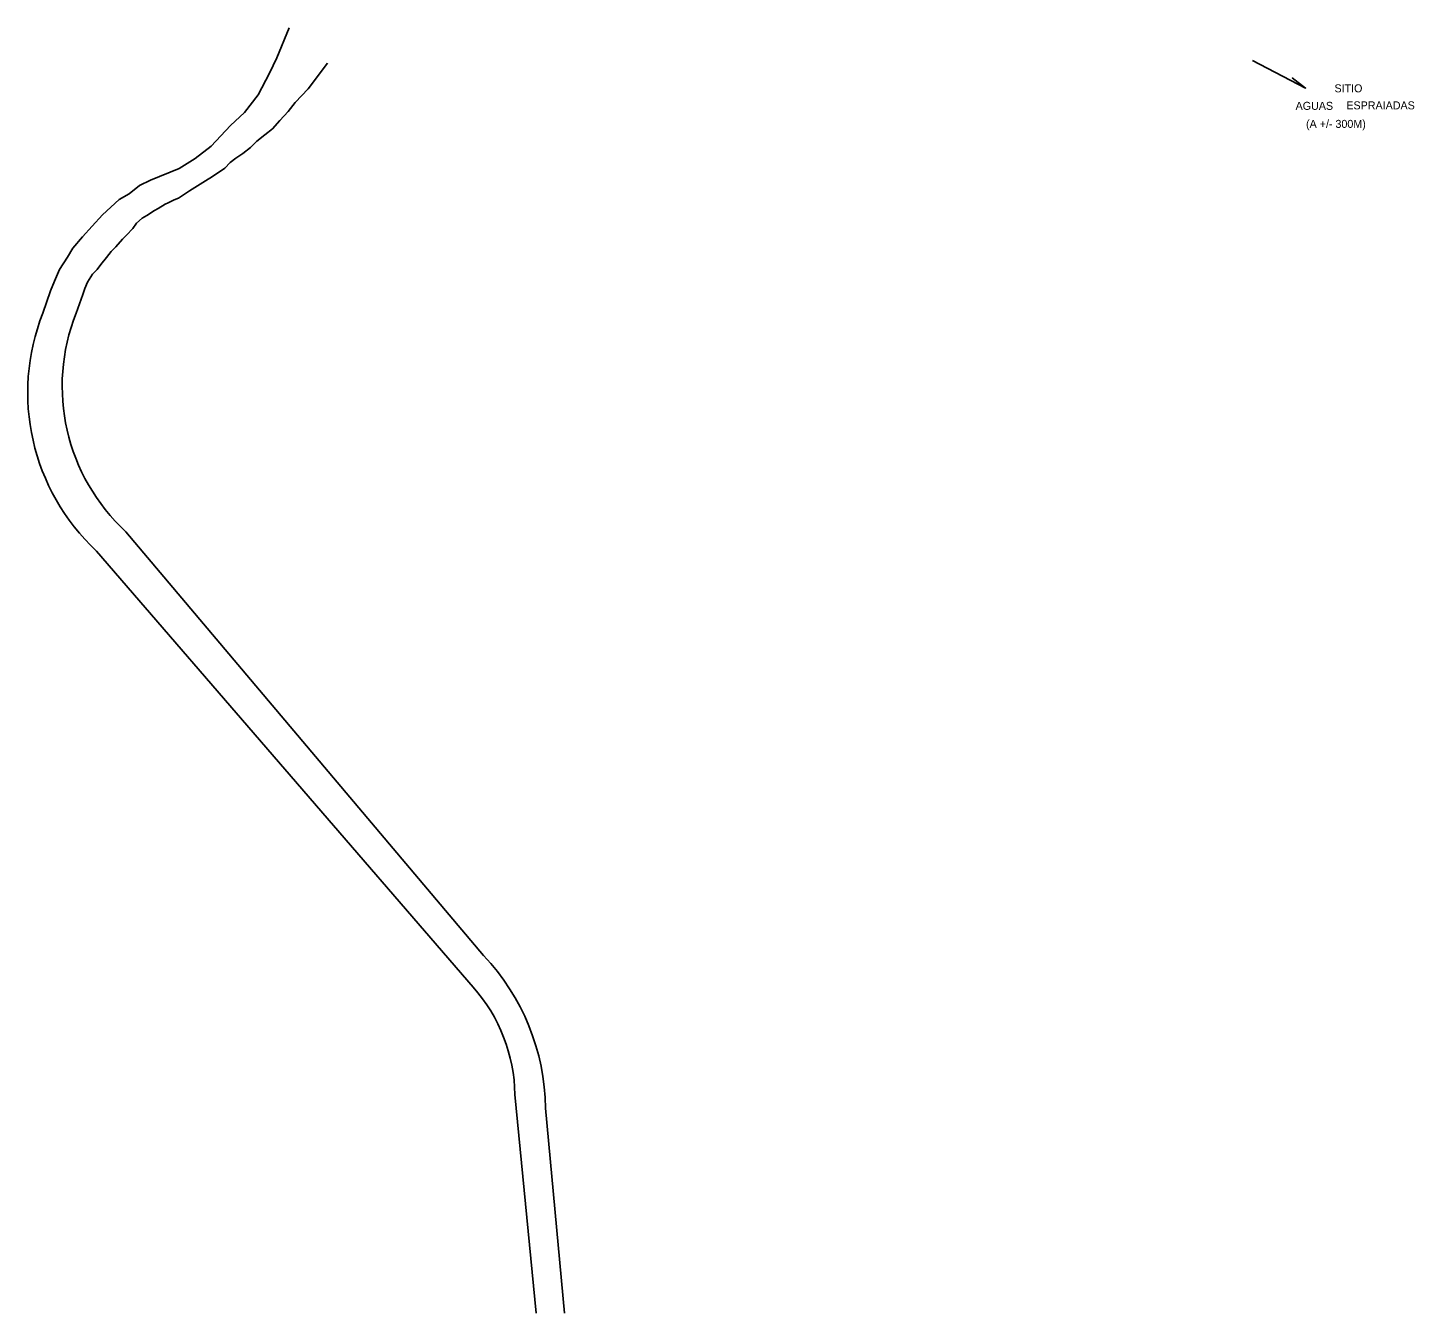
# Model space of a CAD drawing. Extents: x 325899 to 364828, y 7568995 to 7592502.
# Drawn here: x 343420 to 344113, y 7587502 to 7588145 of the extents above; entities that cross this region are included whole.
import ezdxf

# ---------------------------------------------------------------- set-up
doc = ezdxf.new("R2010")
doc.units = 0
doc.layers.add('EDIFIDENTIF', color=7, linetype='Continuous')
doc.layers.add('EDIFOBRAEXIS', color=7, linetype='Continuous')

msp = doc.modelspace()

# ---------------------------------------------------------------- linework, layer by layer
at = {"layer": 'EDIFOBRAEXIS'}
for points in [[(343550.78, 7588144.54), (343544.57, 7588129.48), (343540.95, 7588121.88), (343535.16, 7588111.04), (343528.46, 7588102.21), (343521.32, 7588095.74), (343511.67, 7588085.3), (343503.77, 7588079.22), (343495.72, 7588074.23), (343481.45, 7588068.4), (343475.9, 7588065.59), (343470.77, 7588061.55), (343465.73, 7588058.6), (343457.49, 7588051), (343452.31, 7588045.28), (343447.48, 7588039.97), (343442.58, 7588034.33), (343439.84, 7588029.9), (343435.9, 7588023.62), (343433.41, 7588017.82), (343431.42, 7588013.06), (343427.61, 7588001.91)], [(343569.82, 7588126.87), (343560.26, 7588113.94), (343553.78, 7588107.11), (343550.2, 7588102.74), (343546.04, 7588098.11), (343542.42, 7588094.04), (343538.52, 7588090.93), (343534.51, 7588087.91), (343531.32, 7588084.62), (343527.53, 7588081.67), (343524.09, 7588079.25), (343521.28, 7588077.13), (343518.48, 7588074.37), (343516.46, 7588072.83), (343510.98, 7588069.33), (343510.17, 7588068.8), (343500.95, 7588063.03), (343495.47, 7588059.35), (343493.21, 7588058.44), (343490.23, 7588056.93), (343488.73, 7588056.38), (343485.31, 7588054.11), (343483.38, 7588053.13), (343479.58, 7588050.69), (343477.29, 7588049.33), (343474.43, 7588046.78), (343472.52, 7588044.2), (343469.4, 7588040.83), (343467.41, 7588038.84), (343464.14, 7588035.04), (343461.8, 7588032.74), (343459.42, 7588029.73), (343456.53, 7588026.22), (343454.68, 7588023.73), (343452.47, 7588021.31), (343449.84, 7588017.33), (343448.6, 7588014.14), (343447.52, 7588011.14), (343444.23, 7588001.91), (343444.23, 7588001.91)], [(344032.08, 7588128.2), (344058.69, 7588114.33), (344052.04, 7588119.54), (344052.04, 7588119.54)], [(343469.15, 7587892.52), (343647.83, 7587680.75)], [(343454.42, 7587882.93), (343642.68, 7587664.88)], [(343663.53, 7587611.28), (343674.1, 7587501.91)], [(343678.76, 7587604.47), (343688.38, 7587501.91)]]:
    msp.add_lwpolyline(points, dxfattribs=at)
for centre, radius, start, end in [((343528.48, 7587962.13), 108.44, 158.47859, 226.92006), ((343536.51, 7587965.4), 99.24, 158.41143, 227.25623), ((343566.45, 7587603.34), 112.32, 0.57781, 43.56713), ((343580.43, 7587609.81), 83.11, 1.01466, 41.49948)]:
    msp.add_arc(centre, radius, start, end, dxfattribs=at)

# ---------------------------------------------------------------- texts
at = {"layer": 'EDIFIDENTIF'}
for s, p in [('SITIO', (344073.11, 7588112.24)), ('AGUAS', (344053.68, 7588103.49)), ('ESPRAIADAS', (344079.05, 7588103.72)), ('(A +/- 300M)', (344058.9, 7588094.47))]:
    msp.add_text(s, height=4, dxfattribs=at).set_placement(p)

doc.saveas('drawing.dxf')
